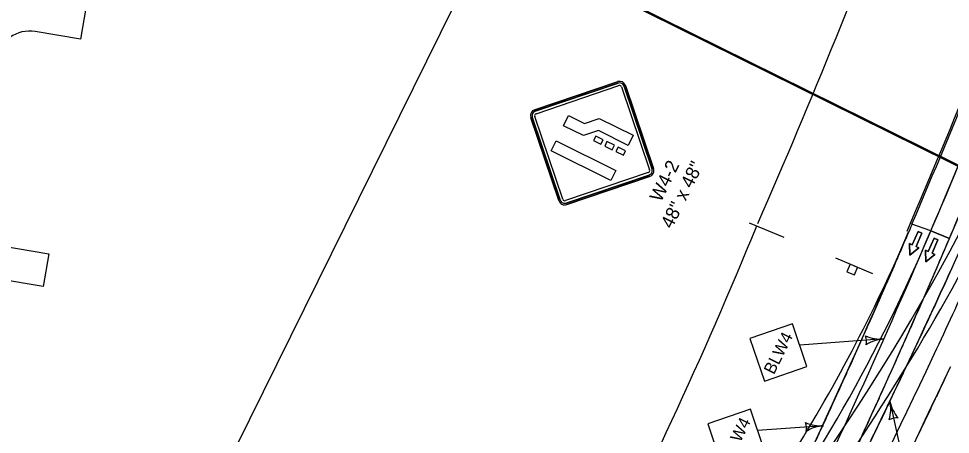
# Model space of a CAD drawing. Extents: x 14097936 to 14128734, y 8632000 to 8683104.
# Drawn here: x 14119231 to 14119790, y 8669847 to 8670096 of the extents above; entities that cross this region are included whole.
import ezdxf

# ---------------------------------------------------------------- set-up
doc = ezdxf.new("R2010")
doc.units = 0
for name, color, linetype in [('Cell', 7, 'Continuous'), ('dsn_stg_shd_prev', 7, 'Continuous'), ('dsnNonPlotable', 7, 'Continuous'), ('dsnPaintExistingBrokenLaneLineWhite', 7, 'Continuous'), ('dsnPaintExistingEdgeLineRightWhite', 7, 'Continuous'), ('dsnPaintPlaceBrokenLaneWhite', 7, 'Continuous'), ('dsnPaintPlaceEdgeLineRightWhite', 7, 'Continuous'), ('dsnPaintPlaceNoPassingYellow', 7, 'Continuous'), ('dsnPaintRemoveChannelizingLaneYellow', 7, 'Continuous'), ('dsnShadingPaved', 7, 'Continuous'), ('dsnStdLabel', 7, 'Continuous'), ('dsnTapeRemoveChannelizingLaneWhite', 7, 'Continuous'), ('dsnTapeRemoveChannelizingLaneYellow', 7, 'Continuous'), ('Level 2', 7, 'Continuous'), ('Level 5', 7, 'Continuous')]:
    doc.layers.add(name, color=color, linetype=linetype)

msp = doc.modelspace()

# ---------------------------------------------------------------- linework, layer by layer
at = {"layer": 'Cell'}
for p, q in [((14119590.08, 8670058.07), (14119540.34, 8670041.24)), ((14119540.34, 8670041.24), (14119590.08, 8670058.07)), ((14119590.38, 8670057.18), (14119540.64, 8670040.35)), ((14119541.15, 8670038.87), (14119590.88, 8670055.7)), ((14119592.46, 8670054.92), (14119609.29, 8670005.18)), ((14119610.77, 8670005.68), (14119593.94, 8670055.42)), ((14119611.66, 8670005.99), (14119594.83, 8670055.72)), ((14119594.83, 8670055.72), (14119611.65, 8670005.98)), ((14119540.34, 8670041.24), (14119540.34, 8670041.24)), ((14119541.15, 8670038.87), (14119541.14, 8670038.87)), ((14119537.99, 8670036.49), (14119554.82, 8669986.76)), ((14119554.82, 8669986.76), (14119537.99, 8670036.49)), ((14119538.88, 8670036.79), (14119555.71, 8669987.06)), ((14119557.19, 8669987.56), (14119540.36, 8670037.29)), ((14119608.5, 8670003.6), (14119558.77, 8669986.77)), ((14119559.27, 8669985.29), (14119609, 8670002.12)), ((14119559.57, 8669984.41), (14119609.3, 8670001.23)), ((14119609.3, 8670001.23), (14119559.57, 8669984.41)), ((14119720.84, 8669952.4), (14119742.95, 8669943.06))]:
    msp.add_line(p, q, dxfattribs=at)
for points in [[(14119540.64, 8670040.35), (14119590.38, 8670057.18)], [(14119541.14, 8670038.87), (14119590.88, 8670055.7)], [(14119592.46, 8670054.92), (14119609.29, 8670005.18)], [(14119593.94, 8670055.42), (14119610.77, 8670005.68)], [(14119555.71, 8669987.06), (14119538.88, 8670036.79)], [(14119557.19, 8669987.56), (14119540.36, 8670037.29)], [(14119608.5, 8670003.6), (14119558.77, 8669986.77)], [(14119609, 8670002.12), (14119559.27, 8669985.29)], [(14119734.03, 8669946.74), (14119729.51, 8669948.65), (14119727.6, 8669944.13), (14119732.12, 8669942.21), (14119734.03, 8669946.74)]]:
    msp.add_lwpolyline(points, dxfattribs=at)
for points in [[(14119570.14, 8670033.03), (14119579.02, 8670036.04), (14119599.46, 8670025.93), (14119596.47, 8670019.88), (14119578.54, 8670028.75), (14119569.66, 8670025.74), (14119557.67, 8670031.67), (14119560.66, 8670037.72)], [(14119553.18, 8670022.59), (14119589.04, 8670004.86), (14119586.05, 8669998.81), (14119550.19, 8670016.54)], [(14119576.93, 8670025.5), (14119575.6, 8670022.81), (14119580.08, 8670020.59), (14119581.41, 8670023.28)], [(14119583.65, 8670022.17), (14119582.32, 8670019.48), (14119586.81, 8670017.27), (14119588.14, 8670019.95)], [(14119590.38, 8670018.85), (14119589.05, 8670016.16), (14119593.53, 8670013.94), (14119594.86, 8670016.63)], [(14119734.03, 8669946.74), (14119729.51, 8669948.65), (14119727.6, 8669944.13), (14119732.12, 8669942.21)]]:
    msp.add_lwpolyline(points, close=True, dxfattribs=at)
for centre, radius, start, end in [((14119591.28, 8670054.52), 3.75, 18.6913, 108.691), ((14119591.28, 8670054.52), 3.75, 18.6913, 108.691), ((14119591.28, 8670054.52), 2.81, 18.6913, 108.691), ((14119591.28, 8670054.52), 2.81, 18.6913, 108.691), ((14119591.28, 8670054.52), 1.25, 18.6913, 108.691), ((14119591.28, 8670054.52), 1.25, 18.6913, 108.691), ((14119541.55, 8670037.69), 3.75, 108.6912, 198.6909), ((14119541.55, 8670037.69), 3.75, 108.6912, 198.6909), ((14119541.55, 8670037.69), 2.81, 108.6912, 198.6909), ((14119541.55, 8670037.69), 2.81, 108.6912, 198.6909), ((14119541.55, 8670037.69), 1.25, 108.6912, 198.6909), ((14119541.55, 8670037.69), 1.25, 108.6912, 198.6909), ((14119608.1, 8670004.78), 1.25, 288.6911, 18.6913), ((14119608.1, 8670004.78), 1.25, 288.6911, 18.6913), ((14119608.1, 8670004.78), 2.81, 288.6911, 18.6913), ((14119608.1, 8670004.78), 2.81, 288.6911, 18.6913), ((14119608.1, 8670004.78), 3.75, 288.6911, 18.6913), ((14119608.1, 8670004.78), 3.75, 288.6911, 18.6913), ((14119558.37, 8669987.96), 1.25, 198.6909, 288.6911), ((14119558.37, 8669987.96), 1.25, 198.6909, 288.6911), ((14119558.37, 8669987.96), 3.75, 198.6909, 288.6911), ((14119558.37, 8669987.96), 3.75, 198.6909, 288.6911), ((14119558.37, 8669987.96), 2.81, 198.6909, 288.6911), ((14119558.37, 8669987.96), 2.81, 198.6909, 288.6911)]:
    msp.add_arc(centre, radius, start, end, dxfattribs=at)
at = {"layer": 'dsn_stg_shd_prev'}
for p, q in [((14119271.21, 8670103.29), (14119267.91, 8670083.56)), ((14119267.91, 8670083.56), (14119240.67, 8670088.13)), ((14119219.24, 8669959.9), (14119248.83, 8669954.95)), ((14119248.83, 8669954.95), (14119245.53, 8669935.22)), ((14119245.53, 8669935.22), (14119216.04, 8669940.16))]:
    msp.add_line(p, q, dxfattribs=at)
msp.add_arc((14119237.36, 8670068.4), 20, 80.4915, 170.4915, dxfattribs=at)
at = {"layer": 'dsnNonPlotable'}
for points in [[(14119282.05, 8670260.59), (14119976.78, 8671665.73), (14120882.16, 8671218.09), (14120187.43, 8669812.95)], [(14119930.17, 8669941), (14120624.9, 8671346.14), (14120172.2, 8671569.96), (14119477.47, 8670164.82)], [(14119315.27, 8668607.09), (14120010, 8670012.23), (14119557.31, 8670236.05), (14118862.58, 8668830.91)]]:
    msp.add_lwpolyline(points, close=True, dxfattribs=at)
at = {"layer": 'dsnPaintExistingBrokenLaneLineWhite'}
for centre, radius, start, end in [((14115455.27, 8671919.94), 4775.43, 334.8735, 335.49516), ((14115457.93, 8671918.7), 4772.49, 331.51238, 334.87343)]:
    msp.add_arc(centre, radius, start, end, dxfattribs=at)
at = {"layer": 'dsnPaintExistingEdgeLineRightWhite'}
for centre, radius, start, end in [((14116594.62, 8671342.65), 3454.16, 336.55764, 340.10427), ((14115457.93, 8671918.7), 4784.49, 331.51238, 334.87343)]:
    msp.add_arc(centre, radius, start, end, dxfattribs=at)
at = {"layer": 'dsnPaintPlaceBrokenLaneWhite'}
msp.add_arc((14115416.69, 8671831.7), 4742.58, 334.09122, 339.391, dxfattribs=at)
at = {"layer": 'dsnPaintPlaceEdgeLineRightWhite'}
msp.add_arc((14115464.82, 8671807.98), 4676.93, 333.43454, 336.83378, dxfattribs=at)
at = {"layer": 'dsnPaintPlaceNoPassingYellow'}
for centre, radius, start, end in [((14115456.71, 8671919.32), 4761.86, 334.13293, 337.35837), ((14115416.69, 8671831.7), 4754.58, 334.83917, 337.17562)]:
    msp.add_arc(centre, radius, start, end, dxfattribs=at)
at = {"layer": 'dsnPaintRemoveChannelizingLaneYellow'}
msp.add_arc((14115570.48, 8671771.3), 4577.36, 336.80891, 339.3131, dxfattribs=at)
at = {"layer": 'dsnShadingPaved'}
for p, q in [((14119777.97, 8669968.74), (14119766.62, 8669972.72)), ((14119777.97, 8669968.74), (14119766.62, 8669972.72)), ((14119789.07, 8669964), (14119777.97, 8669968.74)), ((14119777.97, 8669968.74), (14119789.07, 8669964))]:
    msp.add_line(p, q, dxfattribs=at)
for points in [[(14119766.69, 8669972.69), (14119765.79, 8669970.59), (14119765.29, 8669969.44), (14119763.82, 8669966.01), (14119763.36, 8669964.94), (14119761.85, 8669961.42), (14119761.65, 8669960.94), (14119761.4, 8669960.37), (14119759.88, 8669956.84), (14119759.43, 8669955.81), (14119757.98, 8669952.45), (14119757.9, 8669952.27), (14119757.46, 8669951.25), (14119755.92, 8669947.69), (14119755.48, 8669946.69), (14119754.3, 8669943.97), (14119753.93, 8669943.12), (14119753.5, 8669942.13), (14119751.93, 8669938.55), (14119751.51, 8669937.57), (14119750.6, 8669935.5), (14119749.94, 8669933.98), (14119749.52, 8669933.02), (14119747.93, 8669929.41), (14119747.52, 8669928.47), (14119746.89, 8669927.03), (14119745.92, 8669924.84), (14119745.52, 8669923.92), (14119743.91, 8669920.28), (14119743.51, 8669919.37), (14119743.15, 8669918.57), (14119741.89, 8669915.72), (14119741.5, 8669914.82), (14119739.87, 8669911.16), (14119739.48, 8669910.28), (14119739.41, 8669910.12), (14119737.84, 8669906.6), (14119737.46, 8669905.74), (14119735.81, 8669902.05), (14119735.64, 8669901.67), (14119735.43, 8669901.2), (14119733.77, 8669897.5), (14119733.4, 8669896.66), (14119731.86, 8669893.23), (14119731.73, 8669892.95), (14119731.36, 8669892.13), (14119729.69, 8669888.4), (14119729.32, 8669887.59), (14119728.06, 8669884.8), (14119727.64, 8669883.85), (14119727.28, 8669883.06), (14119725.58, 8669879.31), (14119725.23, 8669878.53), (14119724.25, 8669876.37), (14119723.52, 8669874.77), (14119723.17, 8669874.01), (14119721.45, 8669870.23), (14119721.11, 8669869.48), (14119720.42, 8669867.96), (14119719.38, 8669865.69), (14119719.05, 8669864.96), (14119717.31, 8669861.15), (14119716.98, 8669860.44), (14119716.57, 8669859.55), (14119715.23, 8669856.62), (14119714.91, 8669855.92), (14119713.14, 8669852.09), (14119712.83, 8669851.4), (14119712.71, 8669851.14), (14119711.05, 8669847.56), (14119710.74, 8669846.89), (14119708.96, 8669843.04)], [(14119737.04, 8669846.6), (14119738.38, 8669849.54), (14119738.8, 8669850.44), (14119739.13, 8669851.16), (14119740.87, 8669854.98), (14119741.21, 8669855.72), (14119742.25, 8669857.99), (14119742.95, 8669859.52), (14119743.29, 8669860.28), (14119745.02, 8669864.07), (14119745.37, 8669864.84), (14119746.1, 8669866.45), (14119747.09, 8669868.62), (14119747.44, 8669869.41), (14119749.15, 8669873.17), (14119749.51, 8669873.97), (14119749.94, 8669874.92), (14119751.2, 8669877.73), (14119751.57, 8669878.54), (14119753.25, 8669882.28), (14119753.63, 8669883.11), (14119753.75, 8669883.4), (14119755.3, 8669886.84), (14119755.68, 8669887.69), (14119757.34, 8669891.4), (14119757.55, 8669891.88), (14119757.73, 8669892.26), (14119759.38, 8669895.96), (14119759.77, 8669896.84), (14119761.34, 8669900.36), (14119761.41, 8669900.53), (14119761.81, 8669901.42), (14119763.44, 8669905.1), (14119763.84, 8669906), (14119765.1, 8669908.86), (14119765.46, 8669909.67), (14119765.87, 8669910.59), (14119767.48, 8669914.24), (14119767.89, 8669915.17), (14119768.85, 8669917.37), (14119769.49, 8669918.81), (14119769.91, 8669919.76), (14119771.5, 8669923.38), (14119771.92, 8669924.35), (14119772.59, 8669925.88), (14119773.5, 8669927.96), (14119773.93, 8669928.94), (14119775.5, 8669932.54), (14119775.93, 8669933.54), (14119776.31, 8669934.4), (14119777.49, 8669937.12), (14119777.93, 8669938.14), (14119779.48, 8669941.7), (14119779.92, 8669942.73), (14119780.01, 8669942.92), (14119781.46, 8669946.29), (14119781.91, 8669947.34), (14119783.44, 8669950.88), (14119783.69, 8669951.45), (14119783.9, 8669951.94), (14119785.41, 8669955.47), (14119785.88, 8669956.54), (14119787.35, 8669959.99), (14119787.85, 8669961.15), (14119789.07, 8669964)], [(14119737.04, 8669846.6), (14119738.38, 8669849.54), (14119738.8, 8669850.44), (14119739.13, 8669851.16), (14119740.87, 8669854.98), (14119741.21, 8669855.72), (14119742.25, 8669857.99), (14119742.95, 8669859.52), (14119743.29, 8669860.28), (14119745.02, 8669864.07), (14119745.37, 8669864.84), (14119746.1, 8669866.45), (14119747.09, 8669868.62), (14119747.44, 8669869.41), (14119749.15, 8669873.17), (14119749.51, 8669873.97), (14119749.94, 8669874.92), (14119751.2, 8669877.73), (14119751.57, 8669878.54), (14119753.25, 8669882.28), (14119753.63, 8669883.11), (14119753.75, 8669883.4), (14119755.3, 8669886.84), (14119755.68, 8669887.69), (14119757.34, 8669891.4), (14119757.55, 8669891.88), (14119757.73, 8669892.26), (14119759.38, 8669895.96), (14119759.77, 8669896.84), (14119761.34, 8669900.36), (14119761.41, 8669900.53), (14119761.81, 8669901.42), (14119763.44, 8669905.1), (14119763.84, 8669906), (14119765.1, 8669908.86), (14119765.46, 8669909.67), (14119765.87, 8669910.59), (14119767.48, 8669914.24), (14119767.89, 8669915.17), (14119768.85, 8669917.37), (14119769.49, 8669918.81), (14119769.91, 8669919.76), (14119771.5, 8669923.38), (14119771.92, 8669924.35), (14119772.59, 8669925.88), (14119773.5, 8669927.96), (14119773.93, 8669928.94), (14119775.5, 8669932.54), (14119775.93, 8669933.54), (14119776.31, 8669934.4), (14119777.49, 8669937.12), (14119777.93, 8669938.14), (14119779.48, 8669941.7), (14119779.92, 8669942.73), (14119780.01, 8669942.92), (14119781.46, 8669946.29), (14119781.91, 8669947.34), (14119783.44, 8669950.88), (14119783.69, 8669951.45), (14119783.9, 8669951.94), (14119785.41, 8669955.47), (14119785.88, 8669956.54), (14119787.35, 8669959.99), (14119787.85, 8669961.15), (14119789.07, 8669964)], [(14119742.2, 8669843.3), (14119743.85, 8669846.71), (14119743.95, 8669846.91), (14119744.38, 8669847.8), (14119746.02, 8669851.2), (14119746.56, 8669852.31), (14119748, 8669855.3), (14119748.18, 8669855.69), (14119748.73, 8669856.82), (14119750.34, 8669860.19), (14119750.89, 8669861.33), (14119752.02, 8669863.69), (14119752.5, 8669864.68), (14119753.05, 8669865.84), (14119754.65, 8669869.18), (14119755.21, 8669870.36), (14119756.03, 8669872.09), (14119756.79, 8669873.69), (14119757.36, 8669874.88), (14119758.93, 8669878.19), (14119759.5, 8669879.4), (14119760.03, 8669880.5), (14119761.07, 8669882.7), (14119761.64, 8669883.92), (14119763.2, 8669887.21), (14119763.78, 8669888.45), (14119764, 8669888.91), (14119765.32, 8669891.72), (14119765.91, 8669892.97), (14119767.45, 8669896.23), (14119767.96, 8669897.34), (14119768.04, 8669897.5), (14119769.56, 8669900.75), (14119770.16, 8669902.03), (14119771.67, 8669905.27), (14119771.91, 8669905.77), (14119772.28, 8669906.57), (14119773.78, 8669909.79), (14119774.39, 8669911.1), (14119775.84, 8669914.21), (14119775.88, 8669914.31), (14119776.5, 8669915.64), (14119777.98, 8669918.84), (14119778.6, 8669920.18), (14119779.75, 8669922.66), (14119780.07, 8669923.36), (14119780.7, 8669924.73), (14119782.16, 8669927.89), (14119782.8, 8669929.27), (14119783.64, 8669931.11), (14119784.24, 8669932.42), (14119784.89, 8669933.82), (14119786.32, 8669936.96), (14119786.97, 8669938.37), (14119787.52, 8669939.57), (14119788.4, 8669941.49), (14119789.05, 8669942.92), (14119790.47, 8669946.03)], [(14119790.47, 8669946.03), (14119789.05, 8669942.92), (14119788.4, 8669941.49), (14119787.52, 8669939.57), (14119786.97, 8669938.37), (14119786.32, 8669936.96), (14119784.89, 8669933.82), (14119784.24, 8669932.42), (14119783.64, 8669931.11), (14119782.8, 8669929.27), (14119782.16, 8669927.89), (14119780.7, 8669924.73), (14119780.07, 8669923.36), (14119779.75, 8669922.66), (14119778.6, 8669920.18), (14119777.98, 8669918.84), (14119776.5, 8669915.64), (14119775.88, 8669914.31), (14119775.84, 8669914.21), (14119774.39, 8669911.1), (14119773.78, 8669909.79), (14119772.28, 8669906.57), (14119771.91, 8669905.77), (14119771.67, 8669905.27), (14119770.16, 8669902.03), (14119769.56, 8669900.75), (14119768.04, 8669897.5), (14119767.96, 8669897.34), (14119767.45, 8669896.23), (14119765.91, 8669892.97), (14119765.32, 8669891.72), (14119764, 8669888.91), (14119763.78, 8669888.45), (14119763.2, 8669887.21), (14119761.64, 8669883.92), (14119761.07, 8669882.7), (14119760.03, 8669880.5), (14119759.5, 8669879.4), (14119758.93, 8669878.19), (14119757.36, 8669874.88), (14119756.79, 8669873.69), (14119756.03, 8669872.09), (14119755.21, 8669870.36), (14119754.65, 8669869.18), (14119753.05, 8669865.84), (14119752.5, 8669864.68), (14119752.02, 8669863.69), (14119750.89, 8669861.33), (14119750.34, 8669860.19), (14119748.73, 8669856.82), (14119748.18, 8669855.69), (14119748, 8669855.3), (14119746.56, 8669852.31), (14119746.02, 8669851.2), (14119744.38, 8669847.8), (14119743.95, 8669846.91), (14119743.85, 8669846.71), (14119742.2, 8669843.3)], [(14119789.69, 8669887.15), (14119789.17, 8669886.04), (14119787.63, 8669882.76), (14119787.04, 8669881.5), (14119785.71, 8669878.68), (14119785.49, 8669878.21), (14119784.9, 8669876.96), (14119783.34, 8669873.66), (14119782.76, 8669872.43), (14119781.72, 8669870.22), (14119781.19, 8669869.12), (14119780.61, 8669867.9), (14119779.03, 8669864.57), (14119778.46, 8669863.38), (14119777.7, 8669861.77), (14119776.87, 8669860.03), (14119776.31, 8669858.85), (14119774.71, 8669855.5), (14119774.15, 8669854.33), (14119773.67, 8669853.33), (14119772.54, 8669850.96), (14119771.98, 8669849.81), (14119770.36, 8669846.43)]]:
    msp.add_lwpolyline(points, dxfattribs=at)
for radius, start in [(4565.36, 336.7987), (4577.36, 336.80891), (4577.36, 336.80891)]:
    msp.add_arc((14115570.48, 8671771.3), radius, start, 339.3131, dxfattribs=at)
msp.add_open_spline([(14119789.07, 8669964), (14119790.92, 8669968.32), (14119796.39, 8669981.2), (14119805.42, 8670002.67), (14119816.06, 8670028.43), (14119826.56, 8670054.25), (14119836.9, 8670080.13), (14119847.09, 8670106.08), (14119857.14, 8670132.07), (14119863.71, 8670149.45), (14119866.99, 8670158.14)], degree=3, dxfattribs=at)
msp.add_open_spline([(14119789.07, 8669964), (14119790.92, 8669968.32), (14119796.39, 8669981.2), (14119805.42, 8670002.67), (14119816.06, 8670028.43), (14119826.56, 8670054.25), (14119836.9, 8670080.13), (14119847.09, 8670106.08), (14119857.14, 8670132.07), (14119863.71, 8670149.45), (14119866.99, 8670158.14)], degree=3, dxfattribs=at)
at = {"layer": 'dsnStdLabel'}
for p, q in [((14119668.95, 8669973.46), (14119689.76, 8669964.91)), ((14119749.75, 8669903.84), (14119699.34, 8669900.07)), ((14119753.39, 8669866.49), (14119768.64, 8669796.3)), ((14119713.66, 8669851.85), (14119674.04, 8669848.89))]:
    msp.add_line(p, q, dxfattribs=at)
for points in [[(14119678.09, 8669878.63), (14119703.67, 8669887.28), (14119695.02, 8669912.86), (14119669.44, 8669904.21)], [(14119652.79, 8669827.45), (14119678.36, 8669836.1), (14119669.71, 8669861.68), (14119644.14, 8669853.03)]]:
    msp.add_lwpolyline(points, close=True, dxfattribs=at)
for centre, radius, start, end in [((14115469.5, 8671811.05), 4588.87, 336.3891, 339.4034), ((14116987.75, 8671075.02), 2903.66, 332.64356, 337.66488), ((14119748.04, 8669926.72), 22.95, 246.2011, 274.2724), ((14119730.56, 8669902.4), 8.86, 346.5381, 22.0066), ((14119751.46, 8669880.95), 22.95, 94.2723, 122.3435), ((14119730.96, 8669861.62), 22.95, 344.185, 12.2563), ((14119775.81, 8669871.36), 22.95, 192.2562, 220.3274), ((14119711.95, 8669874.74), 22.95, 246.2011, 274.2724), ((14119694.48, 8669850.42), 8.86, 346.5381, 22.0066), ((14119757.47, 8669847.69), 8.86, 84.522, 119.9904), ((14119715.37, 8669828.97), 22.95, 94.2723, 122.3435)]:
    msp.add_arc(centre, radius, start, end, dxfattribs=at)
at = {"layer": 'dsnTapeRemoveChannelizingLaneWhite'}
for centre, radius, start, end in [((14118559.34, 8670625.19), 1412.15, 319.58068, 337.35767), ((14118856.61, 8670357.32), 988, 327.62991, 336.79664)]:
    msp.add_arc(centre, radius, start, end, dxfattribs=at)
at = {"layer": 'dsnTapeRemoveChannelizingLaneYellow'}
for centre, radius, start, end in [((14118559.34, 8670625.19), 1400.15, 321.68516, 337.35766), ((14118856.5, 8670357.19), 1000, 323.53736, 337.142)]:
    msp.add_arc(centre, radius, start, end, dxfattribs=at)
at = {"layer": 'Level 2'}
for points in [[(14119772.63, 8669967.25), (14119770.34, 8669968.26), (14119766.81, 8669960.26), (14119765.09, 8669961.02), (14119765.43, 8669954.04), (14119770.81, 8669958.49), (14119769.1, 8669959.25)], [(14119782.24, 8669963.21), (14119779.96, 8669964.22), (14119776.42, 8669956.22), (14119774.71, 8669956.98), (14119775.04, 8669950), (14119780.42, 8669954.45), (14119778.71, 8669955.21)]]:
    msp.add_lwpolyline(points, close=True, dxfattribs=at)
at = {"layer": 'Level 5'}
for points in [[(14119769.1, 8669959.25), (14119770.81, 8669958.49), (14119765.43, 8669954.04), (14119765.09, 8669961.02), (14119766.81, 8669960.26), (14119770.34, 8669968.26), (14119772.63, 8669967.25), (14119769.1, 8669959.25)], [(14119778.71, 8669955.21), (14119780.42, 8669954.45), (14119775.04, 8669950), (14119774.71, 8669956.98), (14119776.42, 8669956.22), (14119779.96, 8669964.22), (14119782.24, 8669963.21), (14119778.71, 8669955.21)]]:
    msp.add_lwpolyline(points, dxfattribs=at)

# ---------------------------------------------------------------- texts
at = {"layer": 'Cell'}
for s, p in [('W4-2', (14119616.05, 8669985.41)), ('48" x 48"', (14119622.66, 8669969.45))]:
    msp.add_text(s, height=8, rotation=63.6912, dxfattribs=at).set_placement(p)
at = {"layer": 'dsnStdLabel'}
for s, p in [('BLW4', (14119683.82, 8669882.09)), ('ELW4', (14119658.52, 8669830.91))]:
    msp.add_text(s, height=7.2, rotation=63.6912, dxfattribs=at).set_placement(p)

doc.saveas('drawing.dxf')
